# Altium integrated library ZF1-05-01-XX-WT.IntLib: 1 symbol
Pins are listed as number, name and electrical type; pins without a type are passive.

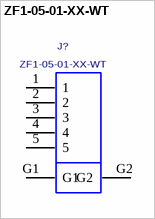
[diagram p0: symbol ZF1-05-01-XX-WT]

## ZF1-05-01-XX-WT
designator J?
ZERO INSERTION FORCE 1mm ASSEMBLY, BOTTOM CONTACT.; MANUFACTURER: SAMTEC
footprint ZF1-05-01-XX-WT
pins: 1, 2, 3, 4, 5, G1, G2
